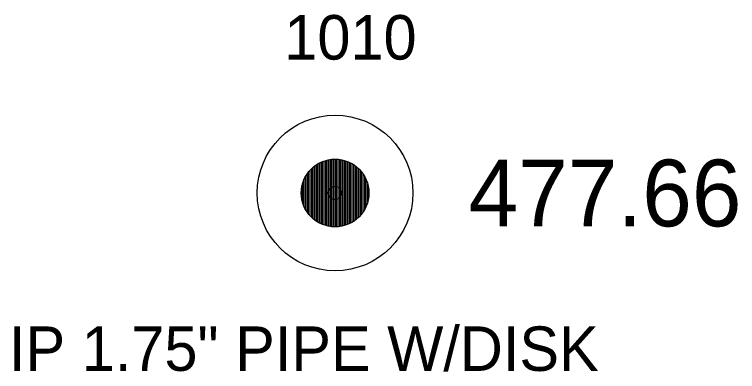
# Model space of a CAD drawing. Extents: x 1611114 to 1617038, y 769445 to 772083.
# Drawn here: x 1617021.28 to 1617037.54, y 770947.32 to 770955.35 of the extents above; entities that cross this region are included whole.
import ezdxf

# ---------------------------------------------------------------- set-up
doc = ezdxf.new("R2010")
doc.units = 0
for name, color, linetype in [('RD_EX_DV_Prop_txCode', 7, 'Continuous'), ('RD_EX_DV_PropPin', 7, 'Continuous'), ('RD_EX_TX_DV_Prop_ELEV', 7, 'Continuous'), ('RD_SMD_Locator', 7, 'Continuous')]:
    doc.layers.add(name, color=color, linetype=linetype)

msp = doc.modelspace()

# ---------------------------------------------------------------- linework, layer by layer
at = {"layer": 'RD_EX_DV_PropPin'}
for p, q in [((1617028.281, 770950.599), (1617028.281, 770952.062)), ((1617028.316, 770950.59), (1617028.316, 770952.071)), ((1617028.351, 770950.583), (1617028.351, 770952.079)), ((1617028.386, 770950.577), (1617028.386, 770952.084)), ((1617028.421, 770950.573), (1617028.421, 770952.088)), ((1617028.456, 770950.57), (1617028.456, 770952.091)), ((1617028.491, 770950.57), (1617028.491, 770952.092)), ((1617028.526, 770950.57), (1617028.526, 770952.091)), ((1617028.561, 770950.573), (1617028.561, 770952.088)), ((1617028.596, 770950.577), (1617028.596, 770952.084)), ((1617028.631, 770950.583), (1617028.631, 770952.079)), ((1617028.666, 770950.59), (1617028.666, 770952.071)), ((1617028.701, 770950.599), (1617028.701, 770952.062)), ((1617028, 770950.748), (1617028, 770951.913)), ((1617028.035, 770950.721), (1617028.035, 770951.94)), ((1617028.071, 770950.696), (1617028.071, 770951.965)), ((1617028.106, 770950.674), (1617028.106, 770951.987)), ((1617028.141, 770950.655), (1617028.141, 770952.006)), ((1617028.176, 770950.638), (1617028.176, 770952.023)), ((1617028.211, 770950.623), (1617028.211, 770952.038)), ((1617028.246, 770950.61), (1617028.246, 770952.051)), ((1617028.736, 770950.61), (1617028.736, 770952.051)), ((1617028.771, 770950.623), (1617028.771, 770952.038)), ((1617028.806, 770950.638), (1617028.806, 770952.023)), ((1617028.841, 770950.655), (1617028.841, 770952.006)), ((1617028.876, 770950.674), (1617028.876, 770951.987)), ((1617028.911, 770950.696), (1617028.911, 770951.965)), ((1617028.946, 770950.721), (1617028.946, 770951.94)), ((1617028.981, 770950.748), (1617028.981, 770951.913)), ((1617027.86, 770950.904), (1617027.86, 770951.757)), ((1617027.895, 770950.856), (1617027.895, 770951.805)), ((1617027.93, 770950.816), (1617027.93, 770951.846)), ((1617027.965, 770950.78), (1617027.965, 770951.881)), ((1617029.016, 770950.78), (1617029.016, 770951.881)), ((1617029.051, 770950.816), (1617029.051, 770951.846)), ((1617029.086, 770950.856), (1617029.086, 770951.805)), ((1617029.121, 770950.904), (1617029.121, 770951.757)), ((1617027.79, 770951.033), (1617027.79, 770951.629)), ((1617027.825, 770950.961), (1617027.825, 770951.7)), ((1617029.156, 770950.961), (1617029.156, 770951.7)), ((1617029.191, 770951.033), (1617029.191, 770951.629)), ((1617027.755, 770951.134), (1617027.755, 770951.527)), ((1617029.226, 770951.134), (1617029.226, 770951.527))]:
    msp.add_line(p, q, dxfattribs=at)
for radius in [1.75, 0.761]:
    msp.add_circle((1617028.491, 770951.331), radius, dxfattribs=at)
at = {"layer": 'RD_SMD_Locator'}
msp.add_circle((1617028.491, 770951.331), 0.15, dxfattribs=at)

# ---------------------------------------------------------------- texts
at = {"layer": 'RD_EX_DV_Prop_txCode'}
for s, p in [('1010', (1617027.349, 770954.331)), ('IP 1.75" PIPE W/DISK', (1617021.16, 770947.331))]:
    msp.add_text(s, height=1, dxfattribs=at).set_placement(p)
at = {"layer": 'RD_EX_TX_DV_Prop_ELEV'}
msp.add_text('477.66', height=1.5, dxfattribs=at).set_placement((1617031.491, 770950.581))

doc.saveas('drawing.dxf')
